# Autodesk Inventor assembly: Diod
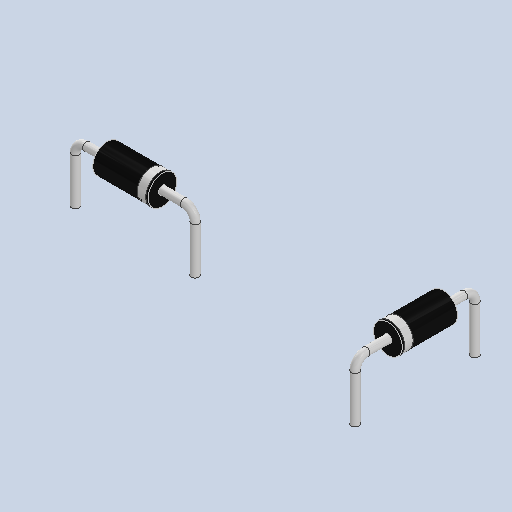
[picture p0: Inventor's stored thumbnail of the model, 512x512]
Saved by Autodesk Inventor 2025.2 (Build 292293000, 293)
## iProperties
Created: 2025-04
Part Number: Diod
Description: PART--DESC
Document SubType Name: Assembly
Designer: BennF
Author: BennF
Revision Number: NONE
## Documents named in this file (2)
- C:\Users\BennF\Nextcloud\Benutzer\CNC JarBeRi\existing parts\Electronics\RepRap A4988 Shied (USE WITHOUT ARDUINO)\reprap-a4988-1.snapshot.1\RepRap\RepRap\Diod.iam
- C:\Users\BennF\Nextcloud\Benutzer\CNC JarBeRi\existing parts\Electronics\RepRap A4988 Shied (USE WITHOUT ARDUINO)\reprap-a4988-1.snapshot.1\RepRap\RepRap\IN4001.ipt
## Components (2 placed, 1 different names)
1. IN4001
2. IN4001:1
